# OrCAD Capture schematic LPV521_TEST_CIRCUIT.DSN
size A; title: LPV521 NanoPower, 1.8-V, RRIO, CMOS Input, Operational Amplifier; rev: 1.0; company: Texas Instruments Inc.; note: Datasheet: SNOSB14D - Aug '09 - Revised Dec '14
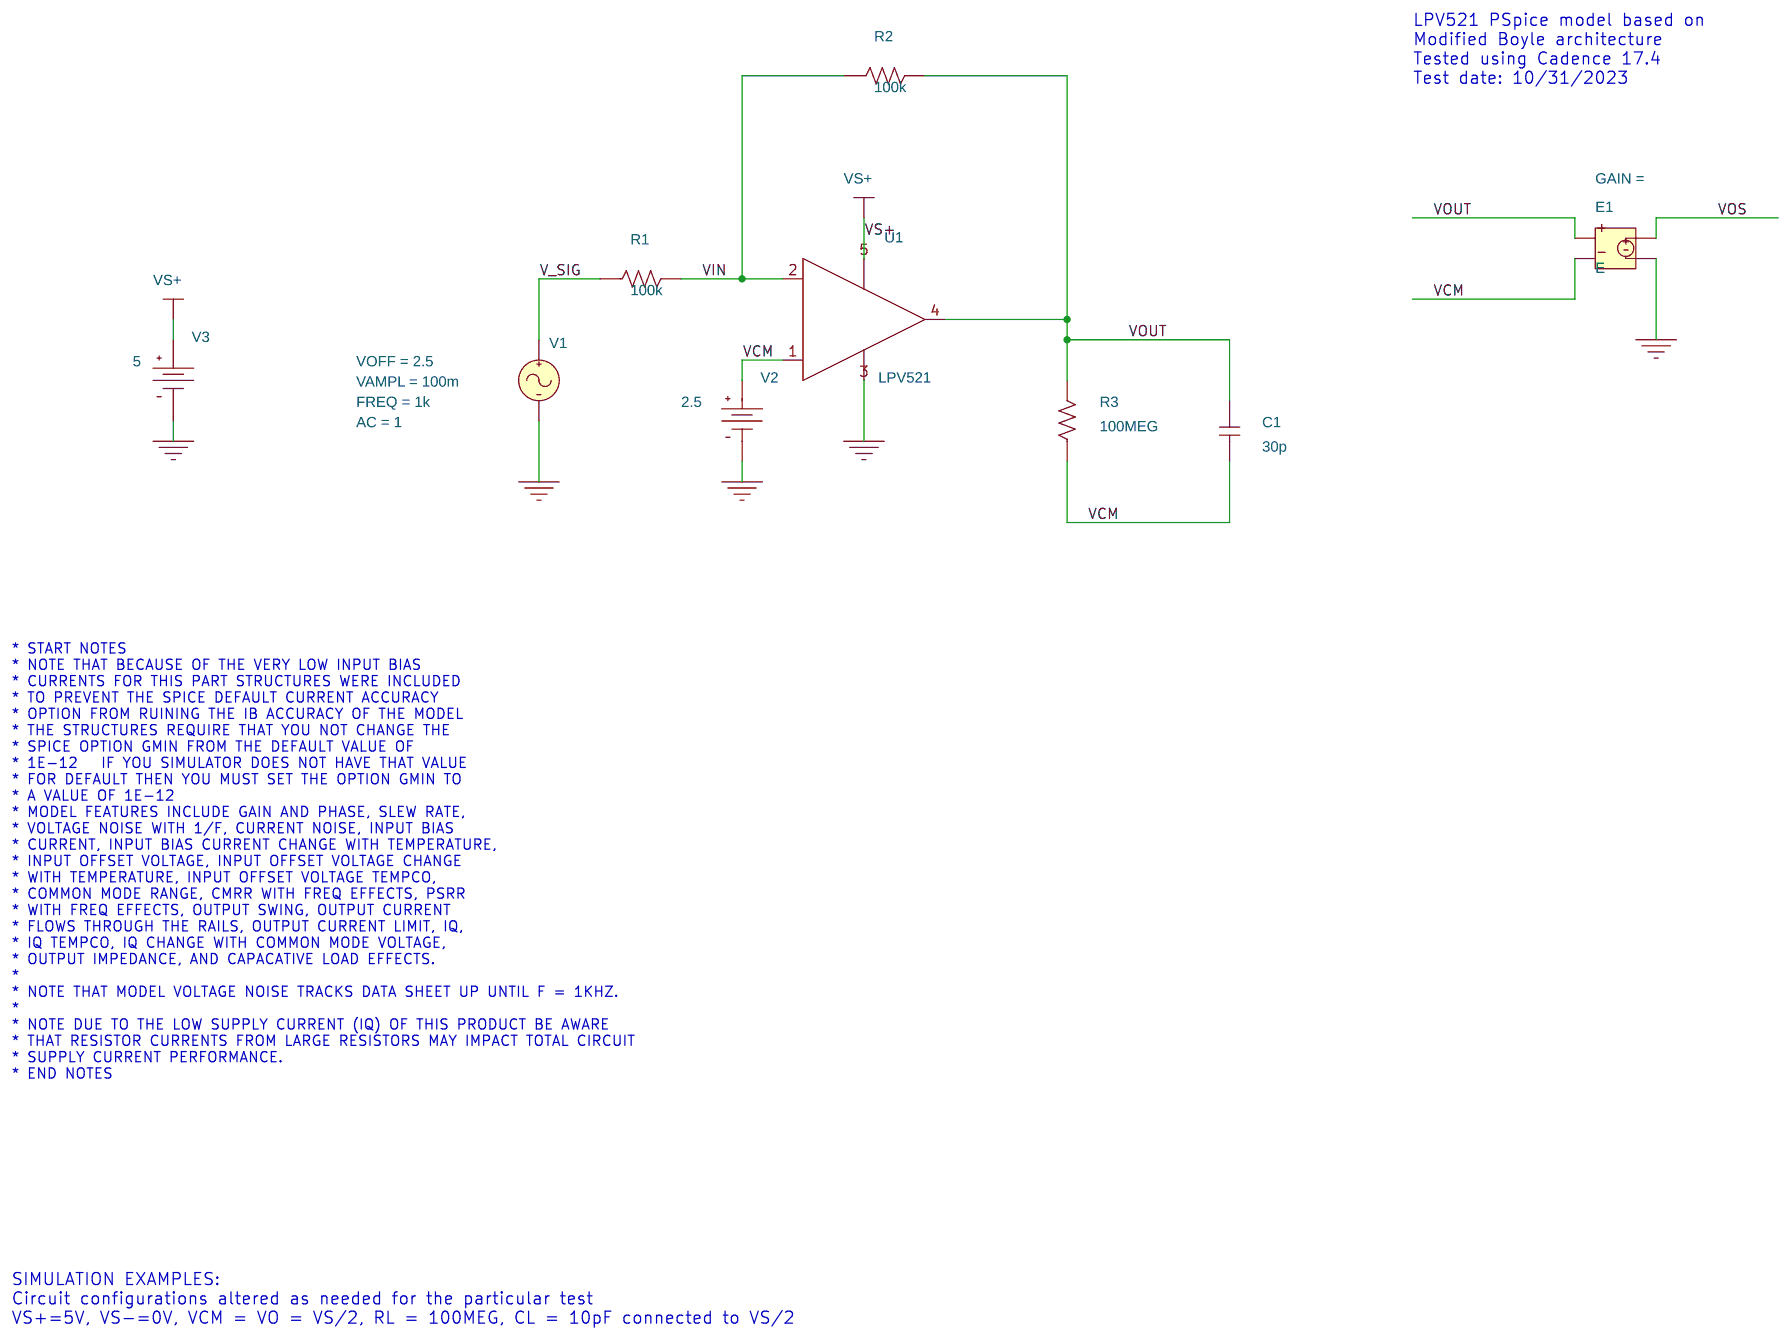
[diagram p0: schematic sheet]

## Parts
C1  30p  [cap196]
E1  E
R1  100k  [AXRC05]
R2  100k  [AXRC05]
R3  100MEG  [AXRC05]
U1  LPV521
V1  VSIN
V2  VDC
V3  VDC

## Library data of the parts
C1 = C
E1 = E
R1-R3 = R
U1 = LPV521
V1 = VSIN: AC: 1; FREQ: 1k; VAMPL: 100m; VOFF: 2.5
V2 = VDC: AppProp: DC$Voltage$0$-1; DC: 2.5
V3 = VDC: AppProp: DC$Voltage$0$-1; DC: 5

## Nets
VIN: R1.2 R2.1 U1.2(-)
0: E1.4 U1.3(V-) V1.2(-) V2.1(-) V3.1(-)
V_SIG: R1.1 V1.1(+)
VCM: C1.1 E1.2 R3.1 U1.1(+) V2.0(+)
VOS: E1.3
VOUT: C1.2 E1.1 R2.2 R3.2 U1.4(OUT)
VS: U1.5(V+) V3.0(+)

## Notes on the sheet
- LPV521 PSpice model based on
  Modified Boyle architecture
  Tested using Cadence 17.4
  Test date: 10/31/2023
- * START NOTES
  * NOTE THAT BECAUSE OF THE VERY LOW INPUT BIAS
  * CURRENTS FOR THIS PART STRUCTURES WERE INCLUDED
  * TO PREVENT THE SPICE DEFAULT CURRENT ACCURACY
  * OPTION FROM RUINING THE IB ACCURACY OF THE MODEL
  * THE STRUCTURES REQUIRE THAT YOU NOT CHANGE THE
  * SPICE OPTION GMIN FROM THE DEFAULT VALUE OF
  * 1E-12   IF YOU SIMULATOR DOES NOT HAVE THAT VALUE
  * FOR DEFAULT THEN YOU MUST SET THE OPTION GMIN TO
  * A VALUE OF 1E-12
  * MODEL FEATURES INCLUDE GAIN AND PHASE, SLEW RATE,
  * VOLTAGE NOISE WITH 1/F, CURRENT NOISE, INPUT BIAS
  * CURRENT, INPUT BIAS CURRENT CHANGE WITH TEMPERATURE,
  * INPUT OFFSET VOLTAGE, INPUT OFFSET VOLTAGE CHANGE
  * WITH TEMPERATURE, INPUT OFFSET VOLTAGE TEMPCO,
  * COMMON MODE RANGE, CMRR WITH FREQ EFFECTS, PSRR
  * WITH FREQ EFFECTS, OUTPUT SWING, OUTPUT CURRENT
  * FLOWS THROUGH THE RAILS, OUTPUT CURRENT LIMIT, IQ,
  * IQ TEMPCO, IQ CHANGE WITH COMMON MODE VOLTAGE,
  * OUTPUT IMPEDANCE, AND CAPACATIVE LOAD EFFECTS.
  *
  * NOTE THAT MODEL VOLTAGE NOISE TRACKS DATA SHEET UP UNTIL F = 1KHZ.
  *
  * NOTE DUE TO THE LOW SUPPLY CURRENT (IQ) OF THIS PRODUCT BE AWARE
  * THAT RESISTOR CURRENTS FROM LARGE RESISTORS MAY IMPACT TOTAL CIRCUIT
  * SUPPLY CURRENT PERFORMANCE.
  * END NOTES
- SIMULATION EXAMPLES:
  Circuit configurations altered as needed for the particular test
  VS+=5V, VS-=0V, VCM = VO = VS/2, RL = 100MEG, CL = 10pF connected to VS/2
